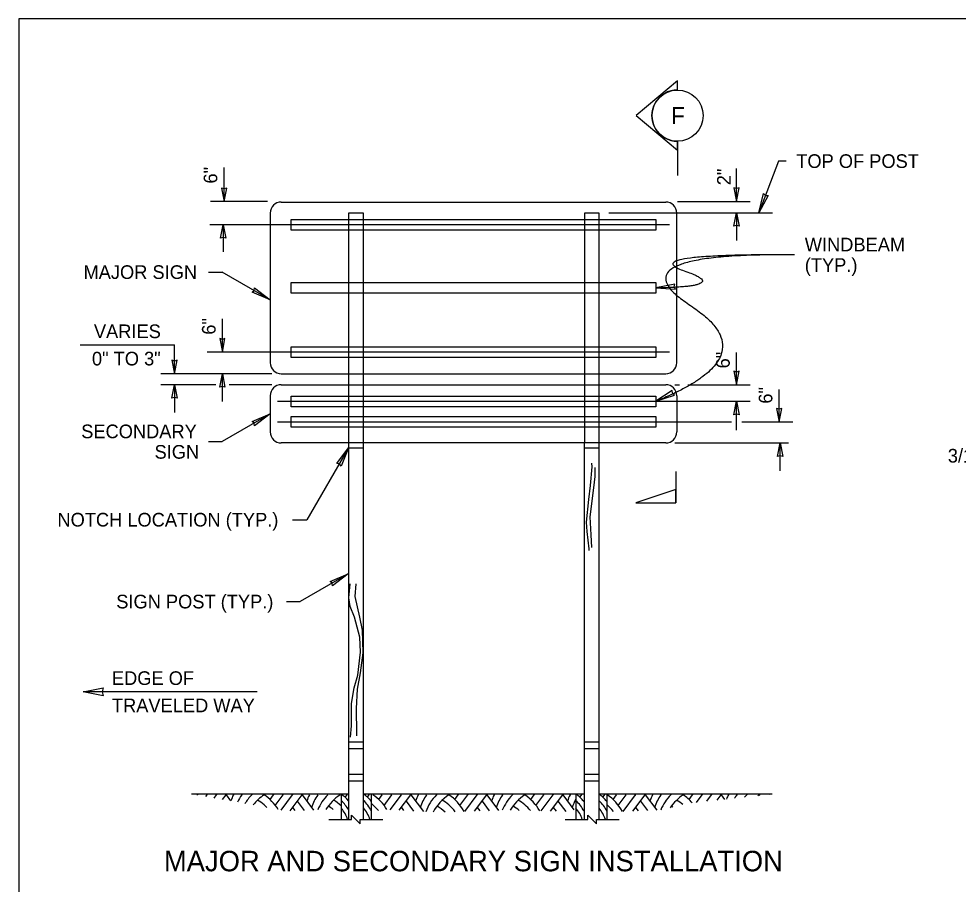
# Model space of a CAD drawing. Extents: x 99862 to 103151, y 100000 to 108076.
# Drawn here: x 99862 to 100964, y 107061 to 108076 of the extents above; entities that cross this region are included whole.
import ezdxf

# ---------------------------------------------------------------- set-up
doc = ezdxf.new("R2010")
doc.units = 0
for name, color, linetype in [('Level 1', 7, 'Continuous'), ('Level 15', 7, 'Continuous'), ('Level 20', 7, 'Continuous'), ('Level 3', 7, 'Continuous'), ('Level 5', 7, 'Continuous'), ('Level 7', 7, 'Continuous'), ('Level 9', 7, 'Continuous')]:
    doc.layers.add(name, color=color, linetype=linetype)

msp = doc.modelspace()

# ---------------------------------------------------------------- linework, layer by layer
at = {"layer": 'Level 1'}
for p, q in [((100169.8, 107860.7), (100620.6, 107860.7)), ((100156.8, 107847.7), (100156.8, 107672.4)), ((100633.6, 107672.4), (100633.6, 107847.7)), ((100169.8, 107659.4), (100620.6, 107659.4)), ((100169.8, 107646.6), (100620.6, 107646.6)), ((100156.8, 107633.6), (100156.8, 107591.3)), ((100633.6, 107633.6), (100633.6, 107591.3)), ((100620.6, 107578.3), (100169.8, 107578.3))]:
    msp.add_line(p, q, dxfattribs=at)
msp.add_lwpolyline([(99862, 105999.5), (103151, 105999.5), (103151, 108075.5), (99862, 108075.5)], close=True, dxfattribs=at)
for centre, start, end in [((100169.8, 107847.7), 90, 180), ((100620.6, 107847.7), 0, 90), ((100169.8, 107672.4), 180, 270), ((100620.6, 107672.4), 270, 0), ((100169.8, 107633.6), 90, 180), ((100620.6, 107633.6), 0, 90), ((100169.8, 107591.3), 180, 270), ((100620.6, 107591.3), 270, 0)]:
    msp.add_arc(centre, 13, start, end, dxfattribs=at)
at = {"layer": 'Level 15'}
for p, q in [((100771.7, 107798.9), (100755.7, 107798.9)), ((100084.5, 107778.6), (100100.5, 107778.6)), ((100156.8, 107746.1), (100100.5, 107778.6)), ((100156.8, 107612.4), (100100.5, 107579.9)), ((100084.5, 107579.9), (100100.5, 107579.9)), ((100248.8, 107572.5), (100199.6, 107488.4)), ((100183.1, 107488.4), (100199.6, 107488.4)), ((100248.3, 107424.9), (100192, 107392.4)), ((100176, 107392.4), (100192, 107392.4))]:
    msp.add_line(p, q, dxfattribs=at)
for points in [[(100761.7, 107908.7), (100752.9, 107908.7), (100729.8, 107848.2)], [(100102.8, 107861.2), (100102.8, 107901.3)], [(100703.6, 107861.5), (100703.6, 107899.9)], [(100153.5, 107861.2), (100086.8, 107861.2)], [(100634.5, 107861.5), (100719.6, 107861.5)], [(100554, 107848.2), (100745.8, 107848.2)], [(100703.6, 107848.2), (100703.6, 107815.5)], [(100624.9, 107834.2), (100085.9, 107834.2)], [(100101.9, 107802.4), (100101.9, 107834.2)], [(100100.8, 107687.3), (100100.8, 107723.8)], [(99934.1, 107693.2), (100044.6, 107693.2)], [(100044.6, 107659.4), (100044.6, 107693.2)], [(100624.9, 107684.8), (100082.8, 107684.8)], [(100703.7, 107646.6), (100703.7, 107684.4)], [(100158.6, 107659.4), (100028.6, 107659.4)], [(100100.7, 107626.8), (100100.7, 107659.4)], [(100092.9, 107646.6), (100028.6, 107646.6)], [(100044.6, 107646.6), (100044.6, 107614.1)], [(100158.6, 107646.6), (100108.6, 107646.6)], [(100631.4, 107646.6), (100636.8, 107646.6)], [(100646.4, 107646.6), (100719.7, 107646.6)], [(100753.7, 107603), (100753.7, 107641)], [(100165.5, 107627.2), (100719.7, 107627.2)], [(100703.7, 107593.3), (100703.7, 107625.3)], [(100165.5, 107603), (100697.7, 107603)], [(100709.7, 107603), (100769.7, 107603)], [(100631.4, 107578.3), (100764.7, 107578.3)], [(100754.7, 107545.8), (100754.7, 107578.3)], [(100225.6, 107137), (100252.1, 107137), (100252.1, 107142.1), (100262.3, 107131.9), (100262.3, 107137), (100288.8, 107137)], [(100502.9, 107137), (100529.4, 107137), (100529.4, 107142.1), (100539.5, 107131.9), (100539.5, 107137), (100566, 107137)]]:
    msp.add_lwpolyline(points, dxfattribs=at)
for points in [[(100102.8, 107861.2), (100105.9, 107876.9), (100102.8, 107876.2), (100099.7, 107876.9)], [(100703.6, 107861.5), (100706.7, 107877.3), (100703.6, 107876.5), (100700.5, 107877.3)], [(100729.8, 107848.2), (100735.2, 107870.6), (100737.6, 107868.5), (100740.7, 107868.4)], [(100703.6, 107848.2), (100706.7, 107832.5), (100703.6, 107833.2), (100700.5, 107832.5)], [(100101.8, 107834.2), (100104.9, 107818.4), (100101.8, 107819.2), (100098.7, 107818.4)], [(100156.8, 107746.1), (100135.5, 107754.9), (100138, 107757), (100138.5, 107760.1)], [(100608.9, 107760.1), (100631.9, 107758.6), (100630.7, 107761.5), (100631.5, 107764.5)], [(100100.7, 107684.8), (100103.8, 107700.6), (100100.7, 107699.8), (100097.6, 107700.6)], [(100044.6, 107659.4), (100047.7, 107675.2), (100044.6, 107674.4), (100041.5, 107675.2)], [(100703.7, 107646.6), (100706.8, 107662.3), (100703.7, 107661.5), (100700.6, 107662.3)], [(100100.7, 107659.4), (100103.8, 107643.7), (100100.7, 107644.4), (100097.6, 107643.7)], [(100044.6, 107646.6), (100047.7, 107630.8), (100044.6, 107631.6), (100041.5, 107630.8)], [(100608.9, 107627.2), (100630.8, 107634.5), (100628.5, 107636.8), (100628.2, 107639.9)], [(100703.7, 107627.2), (100706.8, 107611.5), (100703.7, 107612.2), (100700.6, 107611.5)], [(100753.7, 107603), (100756.8, 107618.7), (100753.7, 107618), (100750.6, 107618.7)], [(100156.8, 107612.4), (100138.5, 107598.4), (100138, 107601.6), (100135.5, 107603.6)], [(100754.7, 107578.3), (100757.8, 107562.6), (100754.7, 107563.3), (100751.6, 107562.6)], [(100248.8, 107572.5), (100240, 107551.3), (100237.9, 107553.7), (100234.8, 107554.2)], [(100248.3, 107424.9), (100230, 107410.9), (100229.4, 107414), (100227, 107416.1)]]:
    msp.add_lwpolyline(points, close=True, dxfattribs=at)
for points in [[(100755.7, 107798.9), (100557.9, 107798.9), (100741.5, 107679.9), (100608.9, 107627.2)], [(100755.7, 107798.9), (100587.6, 107798.9), (100697.6, 107761.1), (100608.9, 107760.1)]]:
    msp.add_open_spline(points, degree=2, dxfattribs=at)
at = {"layer": 'Level 20'}
msp.add_lwpolyline([(99937.4, 107286.6), (99961, 107291.2), (99959.9, 107286.6), (99961, 107282)], close=True, dxfattribs=at)
msp.add_lwpolyline([(100141.7, 107286.6), (99937.4, 107286.6)], dxfattribs=at)
at = {"layer": 'Level 3'}
for p, q in [((100248.8, 107572.5), (100266.4, 107572.5)), ((100524.8, 107572.5), (100542.4, 107572.5))]:
    msp.add_line(p, q, dxfattribs=at)
for points in [[(100249.2, 107848.2), (100266, 107848.2), (100266, 107578.3), (100249.2, 107578.3)], [(100525.6, 107848.2), (100542, 107848.2), (100542, 107578.3), (100525.6, 107578.3)], [(100181.5, 107840.2), (100608.9, 107840.2), (100608.9, 107827.7), (100181.5, 107827.7)], [(100608.9, 107753.8), (100181.5, 107753.8), (100181.5, 107766.3), (100608.9, 107766.3)], [(100181.5, 107690.9), (100608.9, 107690.9), (100608.9, 107678.4), (100181.5, 107678.4)], [(100181.5, 107633.3), (100608.9, 107633.3), (100608.9, 107620.8), (100181.5, 107620.8)], [(100181.5, 107609.4), (100608.9, 107609.4), (100608.9, 107596.9), (100181.5, 107596.9)]]:
    msp.add_lwpolyline(points, close=True, dxfattribs=at)
for points in [[(100266.4, 107137), (100266.4, 107578.3), (100248.8, 107578.3), (100248.8, 107137)], [(100542.4, 107137), (100542.4, 107578.3), (100524.8, 107578.3), (100524.8, 107137)], [(100531, 107452.3), (100530.7, 107454.1), (100528.4, 107474.5), (100527.9, 107485.5), (100530.3, 107512.2), (100532.6, 107528.5), (100534.5, 107550.5), (100534.1, 107554.8)], [(100534.1, 107455.9), (100533.1, 107470.8), (100532.2, 107491.8), (100536.4, 107525.9), (100537.9, 107539), (100537.9, 107549.4)], [(100251.1, 107233.5), (100252.2, 107246.8), (100252.2, 107273), (100255.4, 107291.2), (100259.5, 107306.3), (100262.7, 107333), (100261.8, 107350.6), (100255.8, 107374.3), (100250.4, 107386.8), (100249, 107396.9), (100250.7, 107413.2)], [(100258.3, 107235), (100258.6, 107237.8), (100258.1, 107267), (100259, 107289.6), (100262.7, 107308.8), (100265.9, 107332.5), (100265, 107359.1), (100261.8, 107374.3), (100256.3, 107398.4), (100257.7, 107413.2)], [(100248.8, 107228.2), (100266.4, 107228.2)], [(100248.8, 107220.2), (100266.4, 107220.2)], [(100524.8, 107228.2), (100542.4, 107228.2)], [(100524.8, 107220.2), (100542.4, 107220.2)], [(100248.8, 107190.2), (100266.4, 107190.2)], [(100524.8, 107190.2), (100542.4, 107190.2)], [(100248.8, 107182.2), (100266.4, 107182.2)], [(100524.8, 107182.2), (100542.4, 107182.2)]]:
    msp.add_lwpolyline(points, dxfattribs=at)
at = {"layer": 'Level 5'}
for p, q in [((100240.1, 107166.8), (100240.1, 107137)), ((100275.4, 107166.8), (100275.4, 107137)), ((100515.3, 107166.8), (100515.3, 107137)), ((100551.5, 107166.8), (100551.5, 107137))]:
    msp.add_line(p, q, dxfattribs=at)
for points in [[(100248.8, 107166.7), (100064.4, 107166.7)], [(100524.8, 107166.7), (100266.4, 107166.7)], [(100745.5, 107166.7), (100542.4, 107166.7)]]:
    msp.add_lwpolyline(points, dxfattribs=at)
at = {"layer": 'Level 7'}
for p, q in [((100071.4, 107165.5), (100071.7, 107165.9)), ((100071.7, 107165.9), (100072.3, 107166.7)), ((100081.2, 107163.8), (100082.8, 107165.9)), ((100082.8, 107165.9), (100083.4, 107166.6)), ((100091.1, 107162.1), (100093.9, 107165.9)), ((100093.9, 107165.9), (100094.5, 107166.6)), ((100101, 107160.4), (100105.1, 107165.9)), ((100104.6, 107166.5), (100105.1, 107165.9)), ((100105.1, 107165.9), (100110.4, 107158.7)), ((100149.6, 107165.9), (100149.9, 107166.3)), ((100156.6, 107160.3), (100160.8, 107165.9)), ((100160.8, 107165.9), (100161, 107166.3)), ((100162.7, 107153.6), (100171.9, 107165.9)), ((100169.7, 107148.1), (100183, 107165.9)), ((100171.9, 107165.9), (100172.1, 107166.2)), ((100180.2, 107147.2), (100194.2, 107165.9)), ((100183, 107165.9), (100183.2, 107166.2)), ((100194, 107166.1), (100194.2, 107165.9)), ((100194.2, 107165.9), (100207.5, 107148.1)), ((100244.8, 107162.9), (100247.6, 107166.6)), ((100270.8, 107163.3), (100273.3, 107166.7)), ((100284.1, 107160.3), (100288.3, 107165.9)), ((100288.3, 107165.9), (100288.3, 107165.9)), ((100290.3, 107153.6), (100299.4, 107165.9)), ((100297.5, 107148.4), (100310.6, 107165.9)), ((100299.4, 107165.9), (100299.5, 107166)), ((100308.2, 107147.8), (100321.7, 107165.9)), ((100310.6, 107165.9), (100310.7, 107166)), ((100321.6, 107166), (100321.7, 107165.9)), ((100321.7, 107165.9), (100336.4, 107146.2)), ((100366.3, 107165.9), (100366.5, 107166.2)), ((100373.2, 107160.3), (100377.4, 107165.9)), ((100377.4, 107165.9), (100377.7, 107166.3)), ((100379.3, 107153.6), (100388.5, 107165.9)), ((100385.1, 107146.5), (100399.7, 107165.9)), ((100388.5, 107165.9), (100388.8, 107166.3)), ((100396.5, 107146.8), (100410.8, 107165.9)), ((100399.7, 107165.9), (100400, 107166.3)), ((100410.4, 107166.4), (100410.8, 107165.9)), ((100410.8, 107165.9), (100424.5, 107147.6)), ((100455.3, 107165.9), (100455.8, 107166.5)), ((100462.3, 107160.3), (100466.5, 107165.9)), ((100466.5, 107165.9), (100467, 107166.6)), ((100468.4, 107153.6), (100477.6, 107165.9)), ((100474.7, 107147.1), (100488.8, 107165.9)), ((100477.6, 107165.9), (100478.2, 107166.6)), ((100485.6, 107146.9), (100499.9, 107165.9)), ((100488.8, 107165.9), (100489.4, 107166.7)), ((100499.3, 107166.7), (100499.9, 107165.9)), ((100499.9, 107165.9), (100513, 107148.4)), ((100519.9, 107163.1), (100522.7, 107166.7)), ((100547, 107163), (100549.8, 107166.7)), ((100558.9, 107160.3), (100563.1, 107165.9)), ((100563.1, 107165.9), (100563.1, 107165.9)), ((100565, 107153.6), (100574.2, 107165.9)), ((100570.8, 107146.5), (100585.3, 107165.9)), ((100574.2, 107165.9), (100574.3, 107166)), ((100582.2, 107146.9), (100596.5, 107165.9)), ((100585.3, 107165.9), (100585.4, 107166)), ((100596.3, 107166.1), (100596.5, 107165.9)), ((100596.5, 107165.9), (100610.1, 107147.8)), ((100641, 107165.9), (100641.3, 107166.3)), ((100648, 107160.3), (100652.2, 107165.9)), ((100652.2, 107165.9), (100652.5, 107166.3)), ((100656.7, 107157.1), (100663.3, 107165.9)), ((100663.3, 107165.9), (100663.7, 107166.4)), ((100668.8, 107158.4), (100674.4, 107165.9)), ((100674.4, 107165.9), (100674.8, 107166.4)), ((100680.9, 107159.7), (100685.6, 107165.9)), ((100685.1, 107166.5), (100685.6, 107165.9)), ((100685.6, 107165.9), (100689.5, 107160.6)), ((100730.1, 107165.9), (100730.7, 107166.7)), ((100741.6, 107166.3), (100741.9, 107166.7)), ((100188.6, 107158.5), (100196.6, 107147.7)), ((100274.9, 107158.9), (100275.2, 107159.3)), ((100316.1, 107158.5), (100324.8, 107146.9)), ((100405.2, 107158.5), (100413.6, 107147.3)), ((100494.3, 107158.5), (100503.3, 107146.5)), ((100524, 107158.6), (100524.6, 107159.3)), ((100551.1, 107158.5), (100551.4, 107158.9)), ((100590.9, 107158.5), (100599.2, 107147.4)), ((100183, 107151), (100185.8, 107147.4)), ((100310.6, 107151), (100313.2, 107147.6)), ((100399.7, 107151), (100402.7, 107147)), ((100488.8, 107151), (100492, 107146.7)), ((100585.3, 107151), (100588.3, 107147.1))]:
    msp.add_line(p, q, dxfattribs=at)
for centre, radius, start, end in [((100158.8, 107148.8), 56.4, 161.6629, 162.3566), ((100164.4, 107141.4), 56.4, 154.2265, 162.1106), ((100164.4, 107141.4), 56.4, 153.5392, 154.2266), ((100169.9, 107133.9), 56.4, 145.491, 155.551), ((100169.9, 107133.9), 56.4, 144.799, 145.4911), ((100175.5, 107126.5), 56.4, 135.7127, 148.7927), ((100175.5, 107126.5), 56.4, 134.9964, 135.7128), ((100181.1, 107119.1), 56.4, 123.9036, 141.71), ((100181.1, 107212.7), 56.4, 235.309, 236.0964), ((100118.2, 107119.1), 56.4, 31.7977, 56.0963), ((100247.9, 107148.8), 56.4, 162.1257, 162.3566), ((100253.5, 107141.4), 56.4, 154.2265, 162.3566), ((100253.5, 107141.4), 56.4, 154.0291, 154.2266), ((100259, 107133.9), 56.4, 145.491, 162.3566), ((100259, 107133.9), 56.4, 145.3346, 145.4911), ((100264.6, 107126.5), 56.4, 135.7127, 157.3356), ((100270.2, 107119.1), 56.4, 123.9036, 148.5056), ((100264.6, 107126.5), 56.4, 135.6132, 135.7128), ((100219.2, 107135.4), 37.6, 38.7772, 56.0963), ((100245.2, 107135.8), 37.6, 37.0143, 56.0963), ((100245.7, 107119.1), 56.4, 31.6218, 56.0963), ((100375.4, 107148.8), 56.4, 162.179, 162.3566), ((100381, 107141.4), 56.4, 154.2265, 162.3566), ((100381, 107141.4), 56.4, 154.0024, 154.2266), ((100386.6, 107133.9), 56.4, 145.491, 162.3566), ((100392.1, 107126.5), 56.4, 135.7127, 159.6922), ((100386.6, 107133.9), 56.4, 145.2, 145.4911), ((100397.7, 107119.1), 56.4, 123.9036, 151.9588), ((100392.1, 107126.5), 56.4, 135.3146, 135.7128), ((100397.7, 107212.7), 56.4, 235.4984, 236.0964), ((100334.8, 107119.1), 56.4, 29.0041, 56.0963), ((100464.5, 107148.8), 56.4, 161.8232, 162.3566), ((100470.1, 107141.4), 56.4, 154.2265, 162.3566), ((100470.1, 107141.4), 56.4, 153.6251, 154.2266), ((100475.7, 107133.9), 56.4, 145.491, 162.3566), ((100481.2, 107126.5), 56.4, 135.7127, 157.8637), ((100475.7, 107133.9), 56.4, 144.7863, 145.4911), ((100486.8, 107119.1), 56.4, 123.9036, 149.3956), ((100481.2, 107126.5), 56.4, 134.8354, 135.7128), ((100486.8, 107212.7), 56.4, 234.9093, 236.0964), ((100423.9, 107119.1), 56.4, 29.8078, 56.0963), ((100553.6, 107148.8), 56.4, 161.4666, 162.3566), ((100559.2, 107141.4), 56.4, 154.2265, 162.3566), ((100559.2, 107141.4), 56.4, 153.2465, 154.2266), ((100494.3, 107135.6), 37.6, 36.4242, 56.0963), ((100521.4, 107135.5), 37.6, 37.0275, 56.0963), ((100520.5, 107119.1), 56.4, 29.1019, 56.0963), ((100650.2, 107148.8), 56.4, 162.148, 162.3566), ((100655.8, 107141.4), 56.4, 154.2265, 162.3566), ((100655.8, 107141.4), 56.4, 153.9633, 154.2266), ((100661.3, 107133.9), 56.4, 145.491, 162.3566), ((100666.9, 107126.5), 56.4, 135.7127, 157.5257), ((100661.3, 107133.9), 56.4, 145.1492, 145.4911), ((100672.5, 107119.1), 56.4, 123.9036, 145.8288), ((100666.9, 107126.5), 56.4, 135.2447, 135.7128), ((100672.5, 107212.7), 56.4, 235.396, 236.0964), ((100609.6, 107119.1), 56.4, 41.597, 56.0963), ((100739.3, 107148.8), 56.4, 161.7301, 162.3566), ((100744.9, 107141.4), 56.4, 154.2265, 159.7254), ((100744.9, 107141.4), 56.4, 153.5199, 154.2266), ((100750.4, 107133.9), 56.4, 145.491, 150.2219), ((100750.4, 107133.9), 56.4, 144.6628, 145.4911), ((100756, 107126.5), 56.4, 135.7127, 139.3836), ((100756, 107126.5), 56.4, 134.6808, 135.7128), ((100761.6, 107119.1), 56.4, 123.9036, 125.6397), ((100761.6, 107212.7), 56.4, 234.7077, 236.0964), ((100698.7, 107119.1), 56.4, 54.8256, 56.0963), ((100112.6, 107111.7), 56.4, 48.9597, 58.5465), ((100112.6, 107111.7), 56.4, 44.4785, 48.9597), ((100201.7, 107111.7), 56.4, 47.3456, 58.5465), ((100215.5, 107130.5), 37.6, 48.9597, 49.1164), ((100215.5, 107130.5), 37.6, 28.2051, 48.9597), ((100241.5, 107130.9), 37.6, 25.3685, 48.9597), ((100240.1, 107111.7), 56.4, 39.2231, 50.6469), ((100329.2, 107111.7), 56.4, 48.9597, 58.5465), ((100329.2, 107111.7), 56.4, 37.6757, 48.9597), ((100418.3, 107111.7), 56.4, 48.9597, 58.5465), ((100418.3, 107111.7), 56.4, 39.2405, 48.9597), ((100564.7, 107133.9), 56.4, 151.8856, 162.3566), ((100490.6, 107130.7), 37.6, 25.0876, 48.9597), ((100517.7, 107130.5), 37.6, 25.766, 48.8681), ((100514.9, 107111.7), 56.4, 38.1643, 49.3087), ((100604, 107111.7), 56.4, 49.2936, 58.5465), ((100196.1, 107104.2), 56.4, 52.0709, 59.3021), ((100211.8, 107125.5), 37.6, 40.9413, 41.3214), ((100211.8, 107125.5), 37.6, 17.8024, 40.9414), ((100237.8, 107125.9), 37.6, 17.1424, 40.9414), ((100323.7, 107104.2), 56.4, 47.439, 59.3021), ((100412.8, 107104.2), 56.4, 50.2539, 59.3021), ((100486.9, 107125.7), 37.6, 17.503, 40.9414), ((100514, 107125.6), 37.6, 17.6888, 40.7166), ((100598.4, 107104.2), 56.4, 57.0602, 59.3021)]:
    msp.add_arc(centre, radius, start, end, dxfattribs=at)
at = {"layer": 'Level 9'}
for p, q in [((100634.4, 108002.6), (100585.9, 107962)), ((100634.4, 107992), (100634.4, 108002.6)), ((100585.9, 107962), (100634.4, 107921.4)), ((100634.4, 107921.4), (100634.4, 107932)), ((100634.4, 107932), (100634.4, 107892)), ((100632.3, 107544.9), (100632.3, 107508.3))]:
    msp.add_line(p, q, dxfattribs=at)
msp.add_lwpolyline([(100632.3, 107523.9), (100585.4, 107508.3), (100632.3, 107508.3)], close=True, dxfattribs=at)
msp.add_circle((100634.4, 107962), 30, dxfattribs=at)
msp.add_arc((100634.4, 107962), 30, 89.9978, 270.0022, dxfattribs=at)

# ---------------------------------------------------------------- texts
at = {"layer": 'Level 20'}
for s, height, p in [('F', 20, (100626.9, 107952)), ('MAJOR SIGN', 16, (99937.9, 107770.6)), ('VARIES', 16, (99950.1, 107701.2)), ('0" TO 3"', 16, (99947.8, 107669.2)), ('SECONDARY', 16, (99935.2, 107583.9)), ('SIGN', 16, (100021.2, 107559.9)), ('3/16" (IN) ALUM. RIVETS', 16, (100951.4, 107555.4)), ('NOTCH LOCATION (TYP.)', 16, (99907.3, 107480.4)), ('SIGN POST (TYP.)', 16, (99976.3, 107384.4)), ('EDGE OF', 16, (99971.2, 107294.7)), ('TRAVELED WAY', 16, (99971.2, 107262.7))]:
    msp.add_text(s, height=height, dxfattribs=at).set_placement(p)
for s, height, rotation, p in [('TOP OF POST', 16, 360, (100773.7, 107900.7)), ('6"', 16, 90, (100094.8, 107882.4)), ('2"', 16, 90, (100696.9, 107880.4)), ('WINDBEAM ', 16, 360, (100783.7, 107802.9)), ('(TYP.)', 16, 360, (100783.7, 107778.9)), ('6"', 16, 90, (100092.8, 107705.2)), ('6"', 16, 90, (100695.7, 107665.7)), ('6"', 16, 90, (100745.7, 107624.4)), ('MAJOR AND SECONDARY SIGN INSTALLATION', 24, 360, (100032.2, 107076.3))]:
    msp.add_text(s, height=height, rotation=rotation, dxfattribs=at).set_placement(p)

doc.saveas('drawing.dxf')
